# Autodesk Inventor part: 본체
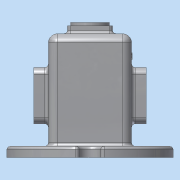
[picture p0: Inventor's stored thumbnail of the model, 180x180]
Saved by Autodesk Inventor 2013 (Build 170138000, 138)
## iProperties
Created: 2018-07
Part Number: 본체
Material: 알루미늄 6061
Document SubType Name: Modeling
Designer: Administrator
Density: 2.71 g/cm^3
Mass: 910.07 g
Surface Area: 1013.39 cm^2
Volume: 335.819 cm^3
Author: Administrator
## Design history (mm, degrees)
sketch "스케치1"
  geometry: L1 (-37, 37)-(37, 37); L2 (37, 37)-(37, -37); L3 (37, -37)-(-37, -37); L4 (-37, -37)-(-37, 37); L5 (-37, 37)-(37, -37); L6 (37, 37)-(-37, -37); 1 further point
  constraints: 12 end point, 2 midpoint, 2 parallel, 1 horizontal, 1 perpendicular
  dimensions: "d0" = 74 distance of L2.end L3.end; "d1" = 74 distance of L1.end L2.end
extrude "돌출1" new body sketch "스케치1" stored distance "d2" = 100; taper "d3" = 0 deg
sketch "스케치2"
  geometry: C1 r 75 at (0, 0); 1 further point
  constraints: 1 centre point, 1 coincident
  dimensions: "d4" = 150 diameter of C1
extrude "돌출2" join sketch "스케치2" distance "d6" = 10; taper "d7" = 0 deg
fillet "모깎기1" dims "d8" = 8
fillet "모깎기2" dims "d9" = 8
sketch "스케치3"
  geometry: L1 (-32, 32)-(32, 32); L2 (32, 32)-(32, -32); L3 (32, -32)-(-32, -32); L4 (-32, -32)-(-32, 32); L5 (-32, 32)-(32, -32); L6 (32, 32)-(-32, -32); C1 r 75 at (0, 0) reference
  constraints: 12 end point, 2 midpoint, 2 parallel, 1 horizontal, 1 perpendicular
  dimensions: "d10" = 64 distance of L2.end L3.end; "d11" = 64 distance of L1.end L2.end
extrude "돌출3" cut sketch "스케치3" distance "d12" = 105; taper "d13" = 0 deg
fillet "모깎기3" dims "d14" = 3
fillet "모깎기4" dims "d15" = 3
fillet "모깎기5" dims "d16" = 3
sketch "스케치4"
  geometry: C1 r 10 at (0, 75); 1 further point
  constraints: 2 vertical alignment, 1 centre point, 1 other
  dimensions: "d17" = 20 diameter of C1
extrude "돌출4" cut sketch "스케치4" stored distance "d18" = 105; taper "d19" = 0 deg
fillet "모깎기6" dims "d23" = 3
fillet "모깎기7" dims "d24" = 3
sketch "스케치5"
  geometry: L1 (42, 32)-(-60, 32) reference; L2 (-5, 32)-(20, 32); L3 (20, 32)-(17.606, 25.422); L4 (17.606, 25.422)-(-5, 25.422); L5 (-5, 25.422)-(-5, 32); L6 (-60, 73.889)-(-60, 12.862) reference; 1 further point
  constraints: 8 end point, 2 point on line, 1 parallel, 1 perpendicular
  dimensions: "d25" = 25 distance of L2.start L2.end; "d26" = 7 distance of L2.end L3.end; "d27" = 70 deg angle of L2 L3; "d73" = 55 distance between parallel lines of L6 L5
revolve "회전1" sketch "스케치5" stored, may be unused: angle "d29" = 90 deg
sketch "스케치6"
  geometry: L1 (4, -22)-(54, -22); L2 (54, -22)-(54, -72); L3 (54, -72)-(4, -72); L4 (4, -72)-(4, -22); L5 (4, -22)-(54, -72); L6 (54, -22)-(4, -72); L7 (41.862, -102)-(102.889, -102) reference; 3 further points
  constraints: 12 end point, 3 midpoint, 2 parallel, 1 horizontal, 1 perpendicular, 1 vertical alignment
  dimensions: "d30" = 50 distance of L2.end L3.end; "d31" = 50 distance of L1.end L2.end; "d69" = 55 distance from line of point (29, -47) L7
extrude "돌출5" join sketch "스케치6" distance "d32" = 13; taper "d33" = 0 deg
node "작업 평면1"
sketch "스케치7"
  geometry: C1 r 17.5 at (0, 0); 1 further point
  constraints: 1 centre point, 1 coincident
  dimensions: "d35" = 35 diameter of C1
extrude "돌출6" join sketch "스케치7" distance "d36" = 3; taper "d37" = 0 deg
sketch "스케치8"
  geometry: L1 (-20, 20)-(20, 20); L2 (20, 20)-(20, -20); L3 (20, -20)-(-20, -20); L4 (-20, -20)-(-20, 20); L5 (-20, 20)-(20, -20); L6 (20, 20)-(-20, -20); C1 r 17.5 at (0, 0) reference
  constraints: 12 end point, 2 midpoint, 2 parallel, 1 horizontal, 1 perpendicular
  dimensions: "d38" = 40 distance of L2.end L3.end; "d39" = 40 distance of L1.end L2.end
extrude "돌출7" join sketch "스케치8" distance "d40" = 7; taper "d41" = 0 deg
sketch "스케치9"
  geometry: L1 (41.862, -102)-(102.889, -102) reference; C1 r 16 at (29, -47); 2 further points
  constraints: 1 centre point, 1 coincident, 1 vertical alignment
  dimensions: "d42" = 32 diameter of C1; "d70" = 55 distance from line of L1 point (29, -47)
extrude "돌출8" cut sketch "스케치9" stored distance "d43" = 7; taper "d44" = 0 deg
sketch "스케치10"
  geometry: C1 r 17.5 at (0, 0) reference; C2 r 14 at (0, 0)
  constraints: 1 centre point, 1 coincident
  dimensions: "d45" = 28 diameter of C2
extrude "돌출9" cut sketch "스케치10" distance "d46" = 4; taper "d47" = 0 deg
sketch "스케치11"
  geometry: C1 r 14 at (0, 0) reference; C2 r 10.5 at (0, 0)
  constraints: 1 centre point, 1 coincident
  dimensions: "d48" = 21 diameter of C2
extrude "돌출10" cut sketch "스케치11" stored distance "d49" = 4; taper "d50" = 0 deg
fillet "모깎기10" dims "d53" = 6
fillet "모깎기11" dims "d54" = 6
fillet "모깎기12" dims "d55" = 3
fillet "모깎기13" dims "d56" = 3
fillet "모깎기14" dims "d57" = 3
chamfer "모따기1" distance "d58" = 1; stored, may be unused: second distance "d59" = 2, angle "d60" = 45 deg
sketch "스케치12"
  geometry: A1 r 6 centre (48, -28) between (54, -28) and (48, -22) reference; A2 r 6 centre (10, -28) between (10, -22) and (4, -28) reference; A3 r 6 centre (10, -66) between (4, -66) and (10, -72) reference; A4 r 6 centre (48, -66) between (48, -72) and (54, -66) reference; 4 further points
  constraints: 4 coincident
hole "구멍1" sketch "스케치12" at (10, -28), (48, -28), (48, -66), (10, -66) diameter "d61" = 3.242; stored, may be unused: countersink angle "d65" = 90 deg, drill point angle "d67" = 118 deg; dims "d62" = 8, "d63" = 4, "d64" = 2, "d66" = 10
sketch "스케치13"
  geometry: L1 (11.5, 18)-(46.5, 18) reference; 2 further points
  constraints: 1 vertical alignment, 1 other
  dimensions: "d68" = 30 distance from line of L1 point (29, -12)
feature "엠보싱1" sketch "스케치13" dims "d71" = 0.5, "d72" = 0
node "솔리드1"
pattern_circular "원형 패턴1" dims angle "d21" = 360 deg
mirror "대칭1"
mirror "대칭2"
mirror "대칭3"
